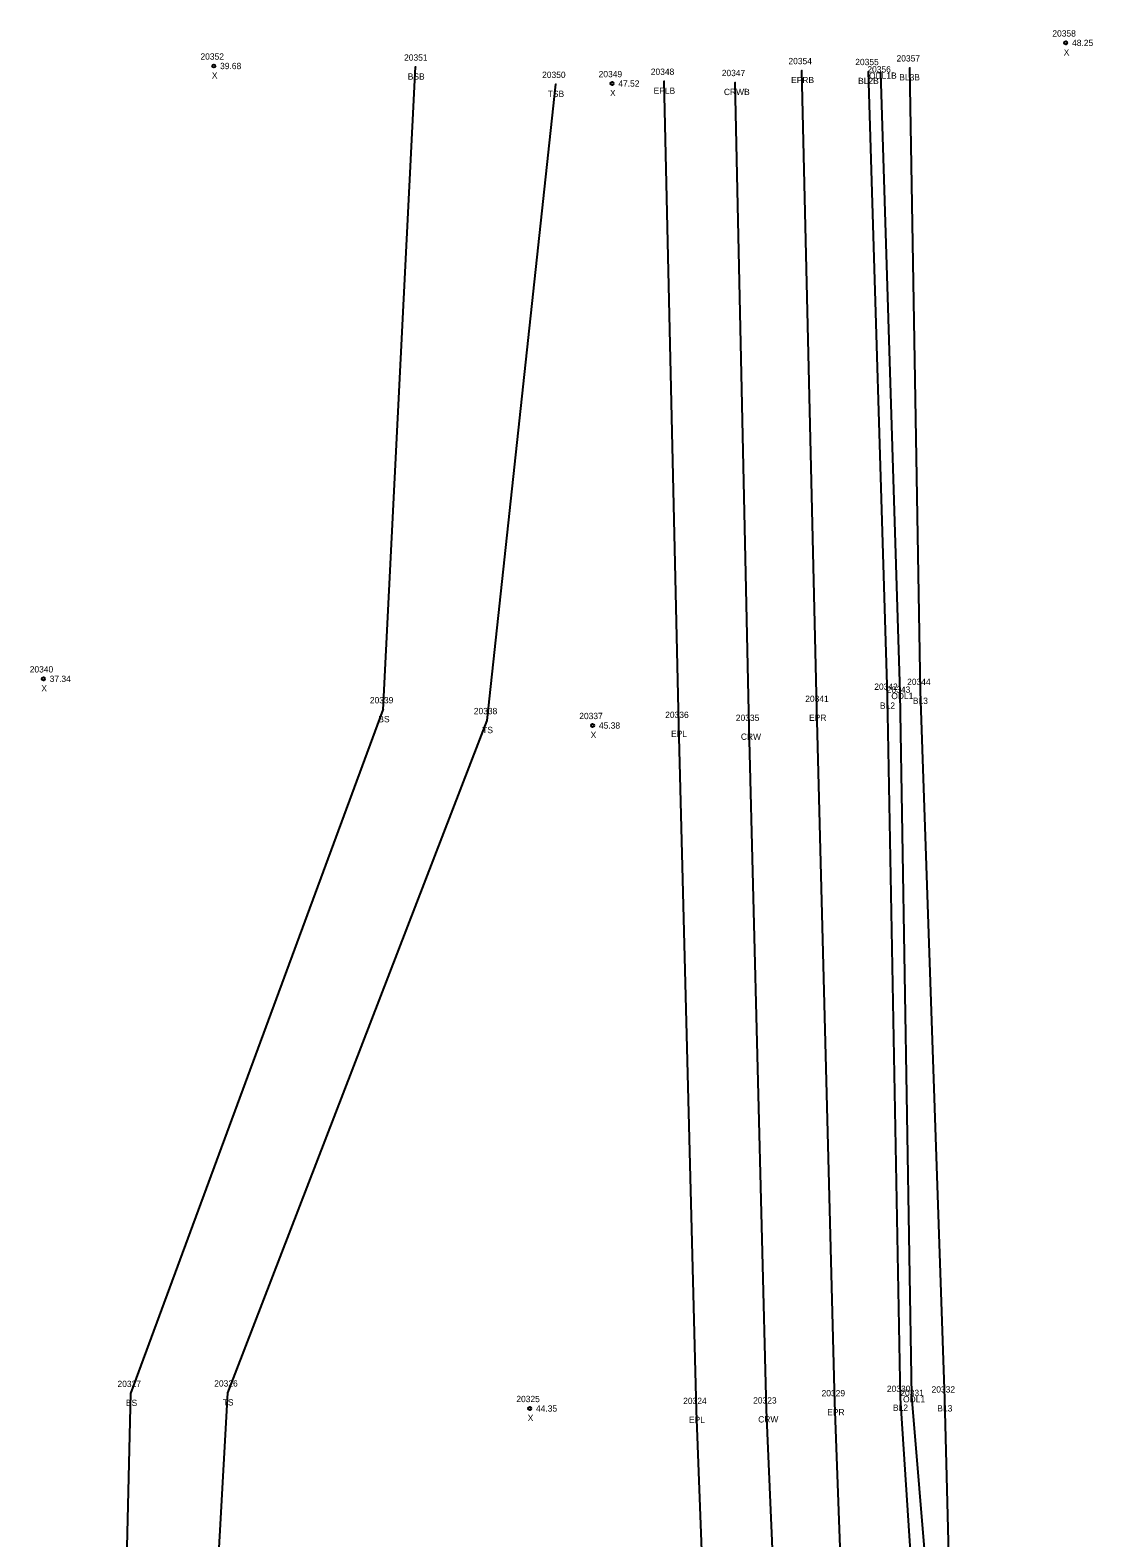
# Model space of a CAD drawing. Extents: x 2445178 to 2446260, y 791158 to 792318.
# Drawn here: x 2445573.2 to 2445741.5, y 792070.4 to 792309.2 of the extents above; entities that cross this region are included whole.
import ezdxf

# ---------------------------------------------------------------- set-up
doc = ezdxf.new("R2010")
doc.units = 0
for name, color, linetype in [('RD_DTM_BkLn1', 7, 'Continuous'), ('RD_DTM_BkLn2', 7, 'Continuous'), ('RD_EX_H2O', 7, 'Continuous'), ('RD_EX_H2O_txCode', 7, 'Continuous'), ('RD_EX_Road', 7, 'Continuous'), ('RD_EX_Road_txCode', 7, 'Continuous'), ('RD_Sketch8', 7, 'Continuous'), ('RD_SMD_Locator', 7, 'Continuous'), ('RD_SMD_Misc', 7, 'Continuous')]:
    doc.layers.add(name, color=color, linetype=linetype)

msp = doc.modelspace()

# ---------------------------------------------------------------- linework, layer by layer
at = {"layer": 'RD_DTM_BkLn1'}
for points in [[(2445734.09, 792026.35), (2445724.31, 792034.74), (2445719.18, 792049.23), (2445718.08, 792092.37), (2445714.21, 792204.46), (2445712.52, 792303.23)], [(2445710.31, 791817.61), (2445703.89, 791871.62), (2445699.09, 791922.95), (2445694.51, 791988.23), (2445692.28, 792033.16), (2445689.82, 792090.63), (2445687.08, 792198.77), (2445684.85, 792300.91)], [(2445728.86, 792017.77), (2445719.5, 792033.81), (2445713.9, 792048.85), (2445711.05, 792092.47), (2445709, 792203.69), (2445705.99, 792302.65)]]:
    msp.add_lwpolyline(points, dxfattribs=at)
at = {"layer": 'RD_DTM_BkLn2'}
for points in [[(2445721.97, 791816.74), (2445696.27, 791809.15), (2445685.63, 791803.83), (2445656.7, 791816.36), (2445642.32, 791839.59), (2445634.31, 791862.06), (2445625.81, 791909.02), (2445601.16, 791980.42), (2445587.75, 792035.69), (2445589.15, 792093.24), (2445629.12, 792201.55), (2445634.25, 792303.36)], [(2445696.53, 791819.13), (2445688.31, 791813.55), (2445675.47, 791816.83), (2445662.11, 791825.5), (2445653.3, 791862.54), (2445641.21, 791910.45), (2445613.64, 791982.42), (2445601.35, 792036.55), (2445604.5, 792093.32), (2445645.58, 792199.83), (2445656.44, 792300.62)]]:
    msp.add_lwpolyline(points, dxfattribs=at)
at = {"layer": 'RD_EX_H2O'}
msp.add_lwpolyline([(2445740.15, 792016.85), (2445730.42, 792021.07), (2445722.34, 792033), (2445716.46, 792048.9), (2445712.84, 792092.81), (2445710.99, 792204.22), (2445707.93, 792302.49)], dxfattribs=at)
at = {"layer": 'RD_EX_Road'}
for points in [[(2445699.57, 791813.34), (2445693.24, 791870.48), (2445688.14, 791921.92), (2445683.42, 791987.19), (2445680.88, 792033.67), (2445678.74, 792090.55), (2445675.91, 792199.23), (2445673.61, 792301.11)], [(2445719.65, 791821.33), (2445720.29, 791823.76), (2445714.87, 791872.94), (2445710.18, 791923.37), (2445705.3, 791989.12), (2445702.81, 792033.07), (2445700.66, 792091.77), (2445697.78, 792201.78), (2445695.41, 792302.8)]]:
    msp.add_lwpolyline(points, dxfattribs=at)
at = {"layer": 'RD_SMD_Locator'}
for centre, radius in [((2445737.21, 792307.18), 0.25), ((2445602.28, 792303.52), 0.25), ((2445634.25, 792303.36), 0.001), ((2445712.52, 792303.23), 0.001), ((2445665.35, 792300.74), 0.25), ((2445673.61, 792301.11), 0.001), ((2445684.85, 792300.91), 0.001), ((2445695.41, 792302.8), 0.001), ((2445705.99, 792302.65), 0.001), ((2445707.93, 792302.49), 0.001), ((2445656.44, 792300.62), 0.001), ((2445575.29, 792206.44), 0.25), ((2445709, 792203.69), 0.001), ((2445710.99, 792204.22), 0.001), ((2445714.21, 792204.46), 0.001), ((2445629.12, 792201.55), 0.001), ((2445697.78, 792201.78), 0.001), ((2445645.58, 792199.83), 0.001), ((2445662.28, 792199.05), 0.25), ((2445675.91, 792199.23), 0.001), ((2445687.08, 792198.77), 0.001), ((2445589.15, 792093.24), 0.001), ((2445604.5, 792093.32), 0.001), ((2445652.31, 792090.85), 0.25), ((2445678.74, 792090.55), 0.001), ((2445689.82, 792090.63), 0.001), ((2445700.66, 792091.77), 0.001), ((2445711.05, 792092.47), 0.001), ((2445712.84, 792092.81), 0.001), ((2445718.08, 792092.37), 0.001)]:
    msp.add_circle(centre, radius, dxfattribs=at)

# ---------------------------------------------------------------- texts
at = {"layer": 'RD_EX_H2O_txCode'}
for s, p in [('20356', (2445705.79, 792302.49)), ('ODL1B', (2445706.05, 792301.49)), ('20343', (2445708.87, 792204.22)), ('ODL1', (2445709.58, 792203.22)), ('20331', (2445711.01, 792092.81)), ('ODL1', (2445711.44, 792091.81))]:
    msp.add_text(s, height=1, dxfattribs=at).set_placement(p)
at = {"layer": 'RD_EX_Road_txCode'}
for s, p in [('20348', (2445671.49, 792302.11)), ('20354', (2445693.29, 792303.8)), ('EPRB', (2445693.71, 792300.8)), ('EPLB', (2445671.93, 792299.11)), ('20341', (2445695.95, 792202.78)), ('20336', (2445673.77, 792200.23)), ('EPR', (2445696.55, 792199.78)), ('EPL', (2445674.7, 792197.23)), ('20329', (2445698.54, 792092.77)), ('20324', (2445676.62, 792091.55)), ('EPR', (2445699.43, 792089.77)), ('EPL', (2445677.54, 792088.55))]:
    msp.add_text(s, height=1, dxfattribs=at).set_placement(p)
at = {"layer": 'RD_Sketch8'}
for s, p in [('20358', (2445735.09, 792308.18)), ('20352', (2445600.17, 792304.52)), ('X', (2445736.89, 792305.18)), ('48.25', (2445738.21, 792306.68)), ('39.68', (2445603.28, 792303.02)), ('X', (2445601.97, 792301.52)), ('20349', (2445663.23, 792301.74)), ('47.52', (2445666.35, 792300.24)), ('X', (2445665.03, 792298.74)), ('20340', (2445573.13, 792207.44)), ('X', (2445574.97, 792204.44)), ('37.34', (2445576.29, 792205.94)), ('20337', (2445660.16, 792200.05)), ('X', (2445661.96, 792197.05)), ('45.38', (2445663.28, 792198.55)), ('20325', (2445650.2, 792091.85)), ('44.35', (2445653.31, 792090.35)), ('X', (2445652, 792088.85))]:
    msp.add_text(s, height=1, dxfattribs=at).set_placement(p)
at = {"layer": 'RD_SMD_Misc'}
for s, p in [('20351', (2445632.42, 792304.36)), ('20355', (2445703.87, 792303.65)), ('20357', (2445710.41, 792304.23)), ('BSB', (2445633, 792301.36)), ('20350', (2445654.28, 792301.62)), ('20347', (2445682.73, 792301.91)), ('BL2B', (2445704.32, 792300.65)), ('BL3B', (2445710.85, 792301.23)), ('TSB', (2445655.17, 792298.62)), ('CRWB', (2445683.07, 792298.91)), ('20342', (2445706.88, 792204.69)), ('20344', (2445712.09, 792205.46)), ('20339', (2445627, 792202.55)), ('BL2', (2445707.79, 792201.69)), ('BL3', (2445713, 792202.46)), ('BS', (2445628.34, 792199.55)), ('20338', (2445643.46, 792200.83)), ('20335', (2445684.96, 792199.77)), ('TS', (2445644.79, 792197.83)), ('CRW', (2445685.76, 792196.77)), ('20327', (2445587.03, 792094.24)), ('20326', (2445602.35, 792094.32)), ('20330', (2445708.89, 792093.47)), ('20332', (2445715.96, 792093.37)), ('BS', (2445588.37, 792091.24)), ('TS', (2445603.7, 792091.32)), ('20323', (2445687.7, 792091.63)), ('BL2', (2445709.85, 792090.47)), ('BL3', (2445716.87, 792090.37)), ('CRW', (2445688.5, 792088.63))]:
    msp.add_text(s, height=1, dxfattribs=at).set_placement(p)

doc.saveas('drawing.dxf')
